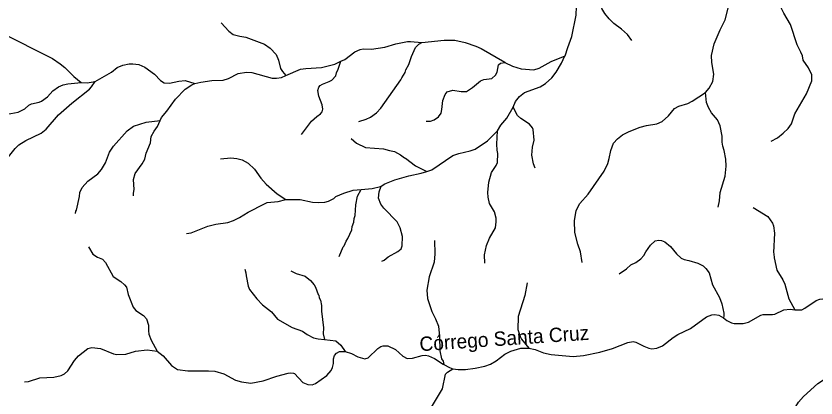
# Model space of a CAD drawing. Extents: x 500 to 555.2, y 9115.7 to 9171.
# Drawn here: x 525.89 to 534.85, y 9152.3 to 9156.58 of the extents above; entities that cross this region are included whole.
import ezdxf
from ezdxf.enums import TextEntityAlignment as Align

# ---------------------------------------------------------------- set-up
doc = ezdxf.new("R2010")
doc.units = 0
doc.header["$LTSCALE"] = 0.064
doc.layers.add('61', color=7, linetype='Continuous')
doc.layers.add('7', color=7, linetype='Continuous', lineweight=25)

msp = doc.modelspace()

# ---------------------------------------------------------------- linework, layer by layer
at = {"layer": '7'}
for points in [[(532.7878, 9156.3031), (532.7368, 9156.369), (532.6693, 9156.4301), (532.5848, 9156.495), (532.5339, 9156.5443), (532.4847, 9156.6036), (532.4493, 9156.6604), (532.435, 9156.6953), (532.4275, 9156.7471), (532.409, 9156.7931), (532.3773, 9156.8276), (532.3485, 9156.8734), (532.3129, 9156.9636), (532.2988, 9157.0908), (532.3025, 9157.167), (532.3286, 9157.2427)], [(533.6097, 9155.7211), (533.6531, 9155.771), (533.6942, 9155.8457), (533.7027, 9155.9249), (533.6831, 9156.0555), (533.6798, 9156.1343), (533.7076, 9156.2655), (533.7748, 9156.423), (533.8305, 9156.5345), (533.8719, 9156.6932), (533.9124, 9156.7707), (533.97, 9156.8567), (533.9963, 9156.9157), (534.0371, 9157.0717), (534.0488, 9157.1525), (534.0555, 9157.2876)], [(534.3476, 9155.1759), (534.4173, 9155.2137), (534.4818, 9155.264), (534.5368, 9155.3171), (534.5716, 9155.3701), (534.6099, 9155.482), (534.7401, 9155.704), (534.7999, 9155.8526), (534.7999, 9155.9182), (534.7648, 9155.9954), (534.7051, 9156.0831), (534.6955, 9156.1314), (534.6795, 9156.1731), (534.6355, 9156.2542), (534.561, 9156.4832), (534.4864, 9156.607), (534.4503, 9156.6817), (534.3445, 9156.8364), (534.3025, 9156.9691), (534.2034, 9157.1267), (534.1702, 9157.1648), (534.0854, 9157.2433), (534.0555, 9157.2876)], [(532.039, 9156.1322), (532.0709, 9156.2241), (532.1165, 9156.3481), (532.1642, 9156.585), (532.1657, 9156.6827), (532.1446, 9156.7805), (532.0922, 9156.9282), (532.0823, 9156.9872), (532.0935, 9157.0735), (532.1194, 9157.1505)], [(528.1907, 9156.501), (528.2771, 9156.4068), (528.3245, 9156.3704), (528.3991, 9156.3499), (528.4686, 9156.3398), (528.6757, 9156.2624), (528.7408, 9156.2168), (528.8064, 9156.1463), (528.8313, 9156.0818), (528.8531, 9155.9898), (528.8755, 9155.9562), (528.9163, 9155.9111)], [(524.8233, 9155.7639), (524.8424, 9155.7776), (524.9973, 9155.9311), (525.1638, 9156.0262), (525.3107, 9156.0588), (525.3562, 9156.0851), (525.3922, 9156.1225), (525.4475, 9156.1944), (525.5099, 9156.2973), (525.5426, 9156.3288), (525.578, 9156.3739), (525.6064, 9156.3931), (525.656, 9156.4037), (525.7147, 9156.3943), (526.3014, 9156.1029), (526.3882, 9156.0434), (526.4423, 9155.9988), (526.5412, 9155.8988), (526.6242, 9155.832)], [(529.5312, 9156.0719), (529.5729, 9156.0915), (529.6862, 9156.1746), (529.7448, 9156.2037), (529.7782, 9156.2103), (529.8733, 9156.2071), (530.0235, 9156.2285), (530.145, 9156.266), (530.2762, 9156.2907), (530.309, 9156.2923), (530.4363, 9156.2793)], [(529.7315, 9155.3943), (529.8136, 9155.4214), (529.8611, 9155.446), (529.9291, 9155.4944), (529.9776, 9155.5461), (530.2012, 9155.862), (530.211, 9155.8862), (530.2488, 9155.9443), (530.2585, 9155.9744), (530.2923, 9156.0344), (530.3204, 9156.1245), (530.3671, 9156.2229), (530.4038, 9156.2615), (530.4363, 9156.2793)], [(530.4363, 9156.2793), (530.4379, 9156.2791), (530.6863, 9156.3071), (530.8058, 9156.3051), (530.9199, 9156.2798), (531.0399, 9156.24), (531.0996, 9156.2119), (531.3642, 9156.0592), (531.3668, 9156.0579)], [(531.3668, 9156.0579), (531.4506, 9156.0169), (531.5472, 9155.9869), (531.6902, 9155.9727), (531.7489, 9155.9925), (531.883, 9156.0673), (532.039, 9156.1322)], [(531.4591, 9155.5553), (531.4839, 9155.6188), (531.5289, 9155.675), (531.5852, 9155.7215), (531.7598, 9155.7845), (531.8213, 9155.82), (531.8907, 9155.8845), (531.9416, 9155.9482), (532.0005, 9156.0504), (532.0383, 9156.1303), (532.039, 9156.1322)], [(526.7788, 9155.8425), (526.9647, 9155.947), (527.0276, 9156), (527.0914, 9156.0268), (527.1629, 9156.0414), (527.2019, 9156.0428), (527.2679, 9156.0331), (527.3356, 9156.0027), (527.445, 9155.9249), (527.5134, 9155.8533), (527.553, 9155.8284), (527.6123, 9155.8265), (527.7173, 9155.8494), (527.788, 9155.8544), (527.8943, 9155.8199)], [(528.9163, 9155.9111), (529.0788, 9155.9806), (529.1364, 9155.9904), (529.3143, 9156.002), (529.4612, 9156.0389), (529.5312, 9156.0719)], [(529.0913, 9155.2501), (529.2007, 9155.4004), (529.2604, 9155.4521), (529.303, 9155.481), (529.3211, 9155.5048), (529.3281, 9155.5355), (529.3229, 9155.581), (529.2837, 9155.6795), (529.274, 9155.7439), (529.2838, 9155.78), (529.2999, 9155.7999), (529.3243, 9155.8147), (529.3984, 9155.8424), (529.4292, 9155.8606), (529.4754, 9155.9055), (529.4825, 9155.9396), (529.5016, 9155.9802), (529.5312, 9156.0719)], [(530.4838, 9155.3986), (530.5339, 9155.3992), (530.5747, 9155.4149), (530.6234, 9155.4473), (530.6517, 9155.4887), (530.6617, 9155.5286), (530.67, 9155.6295), (530.6994, 9155.6985), (530.7208, 9155.7295), (530.784, 9155.7476), (530.8779, 9155.7312), (530.9352, 9155.7311), (531.0045, 9155.7777), (531.092, 9155.8506), (531.1319, 9155.8657), (531.2202, 9155.8781), (531.2607, 9155.9155), (531.2812, 9155.9493), (531.2934, 9156.0299), (531.315, 9156.048), (531.3668, 9156.0579)], [(527.8943, 9155.8199), (527.9626, 9155.8368), (528.088, 9155.8544), (528.2142, 9155.8597), (528.2723, 9155.8776), (528.3828, 9155.9328), (528.4744, 9155.948), (528.5336, 9155.9446), (528.7626, 9155.8827), (528.8091, 9155.8822), (528.8674, 9155.8902), (528.9163, 9155.9111)], [(525.7442, 9154.9329), (525.8117, 9155.002), (525.8852, 9155.0933), (525.9276, 9155.1337), (526.0034, 9155.1844), (526.1748, 9155.2668), (526.2333, 9155.3104), (526.3702, 9155.4718), (526.5195, 9155.6029), (526.7167, 9155.7593), (526.7413, 9155.7855), (526.7788, 9155.8425)], [(525.7556, 9155.4714), (525.9189, 9155.501), (525.9926, 9155.5395), (526.0388, 9155.5789), (526.0667, 9155.595), (526.1544, 9155.6137), (526.1819, 9155.6246), (526.2485, 9155.6716), (526.3051, 9155.7412), (526.3695, 9155.7857), (526.4227, 9155.8066), (526.4748, 9155.8184), (526.6242, 9155.832)], [(526.6242, 9155.832), (526.6923, 9155.828), (526.7788, 9155.8425)], [(527.5092, 9155.409), (527.5231, 9155.4414), (527.5813, 9155.5111), (527.6802, 9155.6448), (527.7865, 9155.7579), (527.8634, 9155.8068), (527.8943, 9155.8199)], [(532.2314, 9153.8182), (532.2133, 9153.9362), (532.1806, 9154.0223), (532.1494, 9154.154), (532.1445, 9154.2859), (532.1621, 9154.3982), (532.2048, 9154.4799), (532.2982, 9154.5827), (532.4762, 9154.839), (532.5162, 9154.9242), (532.5331, 9154.9802), (532.5499, 9155.0725), (532.5821, 9155.1518), (532.6272, 9155.2003), (532.6822, 9155.2455), (532.7563, 9155.2852), (532.8782, 9155.3328), (532.9519, 9155.3506), (533.0679, 9155.3689), (533.1257, 9155.3954), (533.1968, 9155.4583), (533.2645, 9155.5424), (533.314, 9155.5673), (533.4119, 9155.5983), (533.4616, 9155.6233), (533.6097, 9155.7211)], [(533.7542, 9154.4361), (533.7683, 9154.5084), (533.7753, 9154.601), (533.8311, 9154.7856), (533.8421, 9154.8942), (533.8389, 9154.9729), (533.8192, 9155.0714), (533.8044, 9155.1186), (533.798, 9155.1632), (533.7978, 9155.232), (533.7765, 9155.3475), (533.7452, 9155.4163), (533.6765, 9155.492), (533.6438, 9155.551), (533.6223, 9155.6106), (533.6097, 9155.7211)], [(531.2843, 9155.292), (531.3199, 9155.3562), (531.3866, 9155.4345), (531.4591, 9155.5553)], [(531.7059, 9154.8742), (531.6865, 9154.9224), (531.6656, 9155.0195), (531.6757, 9155.1092), (531.6949, 9155.1889), (531.6831, 9155.3061), (531.6753, 9155.3258), (531.6419, 9155.3679), (531.5439, 9155.4302), (531.5057, 9155.463), (531.4591, 9155.5553)], [(526.5601, 9154.3652), (526.5644, 9154.3934), (526.5726, 9154.4024), (526.6065, 9154.5581), (526.6087, 9154.6002), (526.6335, 9154.6566), (526.6999, 9154.7287), (526.8092, 9154.812), (526.8528, 9154.8588), (526.8947, 9154.9325), (526.9396, 9155.0518), (526.9845, 9155.1183), (527.14, 9155.2916), (527.2105, 9155.3426), (527.3527, 9155.3868), (527.5092, 9155.409)], [(527.2084, 9154.5644), (527.2085, 9154.5933), (527.2187, 9154.6348), (527.2089, 9154.7452), (527.2281, 9154.8149), (527.3069, 9154.9238), (527.3351, 9154.9735), (527.3519, 9155.0402), (527.3989, 9155.1557), (527.4092, 9155.2264), (527.4424, 9155.2879), (527.4794, 9155.341), (527.5092, 9155.409)], [(530.4916, 9154.8349), (530.5469, 9154.8561), (530.7833, 9155.0139), (530.851, 9155.0377), (530.9763, 9155.0675), (531.0346, 9155.0871), (531.1702, 9155.1782), (531.2839, 9155.2913), (531.2843, 9155.292)], [(531.141, 9153.809), (531.1375, 9153.9019), (531.1603, 9154.0091), (531.1948, 9154.0911), (531.2599, 9154.2054), (531.2701, 9154.2716), (531.2701, 9154.3147), (531.2486, 9154.383), (531.1928, 9154.4795), (531.1785, 9154.5494), (531.1768, 9154.6002), (531.1869, 9154.7156), (531.216, 9154.8237), (531.2675, 9154.9029), (531.2833, 9154.9388), (531.2865, 9155.0365), (531.2786, 9155.0747), (531.2752, 9155.1415), (531.2843, 9155.292)], [(529.6464, 9155.2058), (529.7066, 9155.1527), (529.8078, 9155.1033), (530.0075, 9155.0896), (530.073, 9155.0707), (530.129, 9155.0619), (530.1969, 9155.0246), (530.2421, 9154.9875), (530.2539, 9154.986), (530.3647, 9154.8988), (530.4916, 9154.8349)], [(528.1816, 9154.9777), (528.2989, 9154.9884), (528.3649, 9154.9815), (528.4273, 9154.9661), (528.4943, 9154.9279), (528.5637, 9154.862), (528.6346, 9154.7599), (528.6926, 9154.6955), (528.8159, 9154.5853), (528.9134, 9154.5232)], [(529.9803, 9154.6723), (530.0236, 9154.6982), (530.1332, 9154.7444), (530.2894, 9154.7865), (530.4302, 9154.8164), (530.4916, 9154.8349)], [(528.9134, 9154.5232), (528.9155, 9154.5238), (529.0737, 9154.5218), (529.2139, 9154.4945), (529.2806, 9154.4884), (529.3515, 9154.4941), (529.393, 9154.5057), (529.4527, 9154.5357), (529.4757, 9154.5551), (529.562, 9154.5943), (529.6682, 9154.6276), (529.7577, 9154.6359)], [(529.5125, 9153.8838), (529.5559, 9153.9935), (529.5673, 9154.0055), (529.5889, 9154.055), (529.6099, 9154.0873), (529.6521, 9154.1843), (529.6579, 9154.2196), (529.6757, 9154.2683), (529.6793, 9154.312), (529.6893, 9154.3444), (529.6989, 9154.4631), (529.7147, 9154.5615), (529.7577, 9154.6359)], [(529.7577, 9154.6359), (529.8807, 9154.6474), (529.9756, 9154.6695), (529.9803, 9154.6723)], [(529.9872, 9153.8311), (530.0141, 9153.8453), (530.0587, 9153.8805), (530.1674, 9153.9398), (530.2046, 9153.9723), (530.2168, 9154.0027), (530.2204, 9154.1087), (530.1938, 9154.2065), (530.1594, 9154.2727), (530.0112, 9154.4251), (529.9777, 9154.47), (529.9533, 9154.5392), (529.9581, 9154.6095), (529.9803, 9154.6723)], [(527.8036, 9154.1423), (527.8557, 9154.1487), (528.0406, 9154.2244), (528.1307, 9154.2485), (528.2645, 9154.2672), (528.3292, 9154.2869), (528.3975, 9154.3212), (528.4934, 9154.3824), (528.6744, 9154.4761), (528.7074, 9154.4878), (528.8276, 9154.4998), (528.9134, 9154.5232)], [(534.1446, 9154.4316), (534.308, 9154.3321), (534.3621, 9154.2566), (534.372, 9154.2284), (534.3834, 9154.1469), (534.3703, 9153.9279), (534.3768, 9153.9132), (534.3786, 9153.8707), (534.4097, 9153.7336), (534.4781, 9153.6224), (534.4982, 9153.576), (534.5447, 9153.4107), (534.609, 9153.2867)], [(526.7076, 9153.992), (526.7529, 9153.9124), (526.8074, 9153.8785), (526.8643, 9153.8531), (526.8967, 9153.816), (526.9818, 9153.6607), (527.0666, 9153.6048), (527.1087, 9153.5678), (527.1299, 9153.5413), (527.15, 9153.4597), (527.2071, 9153.3164), (527.2347, 9153.2811), (527.3215, 9153.2237), (527.3549, 9153.1866), (527.3758, 9153.1157), (527.3762, 9153.0531), (527.3825, 9153.0156), (527.4076, 9152.9489), (527.4744, 9152.8239)], [(530.578, 9154.0625), (530.5829, 9153.9133), (530.573, 9153.8221), (530.5196, 9153.6568), (530.4928, 9153.5085), (530.501, 9153.4154), (530.5473, 9153.2708), (530.5887, 9153.1869), (530.6221, 9153.1036), (530.6337, 9152.9895), (530.6372, 9152.8275), (530.6582, 9152.7401), (530.6747, 9152.7142), (530.6838, 9152.6742)], [(532.6465, 9153.691), (532.7267, 9153.7483), (532.7749, 9153.7917), (532.8317, 9153.8188), (532.8891, 9153.8582), (532.9219, 9153.896), (532.9436, 9153.9373), (532.997, 9154.0131), (533.0484, 9154.0604), (533.0904, 9154.0681), (533.1171, 9154.0646), (533.156, 9154.0485), (533.2179, 9153.9986), (533.2854, 9153.9129), (533.3374, 9153.8661), (533.3713, 9153.8516), (533.4226, 9153.8415), (533.5241, 9153.8086), (533.5866, 9153.7791), (533.6165, 9153.7521), (533.651, 9153.7004), (533.6894, 9153.5692), (533.7665, 9153.4256), (533.7944, 9153.3535), (533.816, 9153.2491), (533.8175, 9153.219), (533.8111, 9153.198)], [(528.4563, 9153.7446), (528.4684, 9153.7031), (528.4702, 9153.6685), (528.4916, 9153.5532), (528.5062, 9153.5172), (528.5904, 9153.4116), (528.6533, 9153.3455), (528.7547, 9153.2637), (528.8202, 9153.182), (528.9848, 9153.0909), (529.1003, 9153.0491), (529.1548, 9153.0115), (529.2252, 9152.9761), (529.2776, 9152.9623), (529.3455, 9152.9549)], [(528.9691, 9153.7258), (529.0295, 9153.6958), (529.1323, 9153.6628), (529.1908, 9153.6148), (529.2329, 9153.5662), (529.2463, 9153.5426), (529.2748, 9153.4582), (529.282, 9153.4508), (529.2889, 9153.4223), (529.3032, 9153.3955), (529.3146, 9153.3379), (529.315, 9153.2729), (529.3346, 9153.0879), (529.3315, 9153.0177), (529.3455, 9152.9549)], [(531.6158, 9153.5887), (531.5898, 9153.4476), (531.5142, 9153.2135), (531.5118, 9153.0691), (531.5383, 9152.9875), (531.5536, 9152.9599), (531.635, 9152.8575)], [(534.609, 9153.2867), (534.6885, 9153.2891), (534.7243, 9153.3079), (534.8477, 9153.3923), (534.8897, 9153.4072), (534.991, 9153.4184), (535.0625, 9153.4086), (535.121, 9153.3876), (535.2403, 9153.3006), (535.3137, 9153.2587), (535.3459, 9153.2223), (535.3818, 9153.1947), (535.4304, 9153.172), (535.5651, 9153.1674), (535.7538, 9153.1001)], [(534.3599, 9153.2349), (534.3867, 9153.2399), (534.4865, 9153.2892), (534.558, 9153.2956), (534.609, 9153.2867)], [(531.635, 9152.8575), (531.7057, 9152.8419), (531.799, 9152.8066), (531.8827, 9152.7877), (532.1282, 9152.7642), (532.2447, 9152.7761), (532.4282, 9152.815), (532.5698, 9152.8546), (532.7431, 9152.9231), (532.8007, 9152.9329), (532.8317, 9152.9264), (532.9217, 9152.8799), (532.9779, 9152.858), (533.009, 9152.8527), (533.0665, 9152.8573), (533.1313, 9152.8851), (533.2505, 9152.9798), (533.3009, 9153.0134), (533.4425, 9153.0794), (533.6228, 9153.2078), (533.6824, 9153.2313), (533.7116, 9153.2347), (533.7602, 9153.2265), (533.8111, 9153.198)], [(533.8111, 9153.198), (533.8483, 9153.1697), (533.9032, 9153.1436), (533.9301, 9153.1351), (534.0333, 9153.1361), (534.0928, 9153.1486), (534.2292, 9153.2266), (534.2562, 9153.2348), (534.3599, 9153.2349)], [(534.7088, 9152.3184), (534.8696, 9152.4626), (534.9432, 9152.5107), (534.9701, 9152.5211), (535.1467, 9152.5563), (535.2429, 9152.5903), (535.2987, 9152.6231), (535.4118, 9152.7076), (535.4901, 9152.7789), (535.5353, 9152.8352), (535.599, 9152.9396), (535.6493, 9153.0014), (535.7332, 9153.09), (535.7538, 9153.1001)], [(529.3455, 9152.9549), (529.474, 9152.941), (529.5297, 9152.8935), (529.5793, 9152.8202)], [(525.9903, 9152.4809), (526.0351, 9152.4866), (526.1629, 9152.5263), (526.3198, 9152.5345), (526.399, 9152.5543), (526.437, 9152.5714), (526.4731, 9152.6058), (526.5495, 9152.7214), (526.5949, 9152.7735), (526.6973, 9152.8542), (526.7431, 9152.8657), (526.8407, 9152.856), (526.9852, 9152.7956), (527.0218, 9152.7887), (527.1229, 9152.7919), (527.2325, 9152.8248), (527.3624, 9152.841), (527.4744, 9152.8239)], [(527.4744, 9152.8239), (527.5418, 9152.7739), (527.6337, 9152.6657), (527.702, 9152.6201), (527.8178, 9152.6051), (528.0482, 9152.6067), (528.1202, 9152.6017), (528.2192, 9152.5721), (528.3511, 9152.5), (528.4168, 9152.4818), (528.5237, 9152.4672), (528.6595, 9152.492), (528.8123, 9152.546), (528.9395, 9152.5799), (528.9663, 9152.583), (528.9992, 9152.5804), (529.0126, 9152.5743), (529.1062, 9152.473), (529.1609, 9152.4509), (529.2083, 9152.4478), (529.2475, 9152.464), (529.3728, 9152.5532), (529.4201, 9152.6089), (529.438, 9152.6438), (529.4476, 9152.6864), (529.4495, 9152.7393), (529.4582, 9152.7769), (529.4814, 9152.8029), (529.5145, 9152.8209), (529.5772, 9152.8209), (529.5793, 9152.8202)], [(529.5793, 9152.8202), (529.6479, 9152.7985), (529.7194, 9152.7613), (529.7967, 9152.7395), (529.8344, 9152.7518), (529.9428, 9152.8551), (529.9772, 9152.8769), (530.0046, 9152.8838), (530.0547, 9152.8837), (530.1434, 9152.8451), (530.2221, 9152.7691), (530.274, 9152.7415), (530.3326, 9152.7479), (530.4409, 9152.7772), (530.477, 9152.7787), (530.5109, 9152.7725), (530.5774, 9152.7415), (530.6738, 9152.6795), (530.6838, 9152.6742)], [(530.7828, 9152.6288), (530.8417, 9152.62), (530.925, 9152.6197), (531.0334, 9152.6343), (531.1416, 9152.6573), (531.2063, 9152.6783), (531.2685, 9152.715), (531.3667, 9152.7926), (531.4343, 9152.8264), (531.5441, 9152.8593), (531.635, 9152.8575)], [(530.6838, 9152.6742), (530.7444, 9152.6421), (530.7828, 9152.6288)], [(530.2731, 9151.6413), (530.3526, 9151.7253), (530.3964, 9151.7959), (530.4285, 9151.8762), (530.4518, 9152.0085), (530.4763, 9152.0866), (530.6682, 9152.4049), (530.6997, 9152.5688), (530.7219, 9152.5895), (530.7828, 9152.6288)], [(534.1665, 9151.8387), (534.2314, 9151.8934), (534.4944, 9152.0346), (534.5441, 9152.0687), (534.591, 9152.1363), (534.6033, 9152.1752), (534.6513, 9152.2544), (534.7088, 9152.3184)]]:
    msp.add_lwpolyline(points, dxfattribs=at)

# ---------------------------------------------------------------- texts
at = {"layer": '61'}
msp.add_text('Córrego Santa Cruz', height=0.16, rotation=3.9, dxfattribs=at).set_placement((531.3645, 9152.8884), align=Align.CENTER)

doc.saveas('drawing.dxf')
